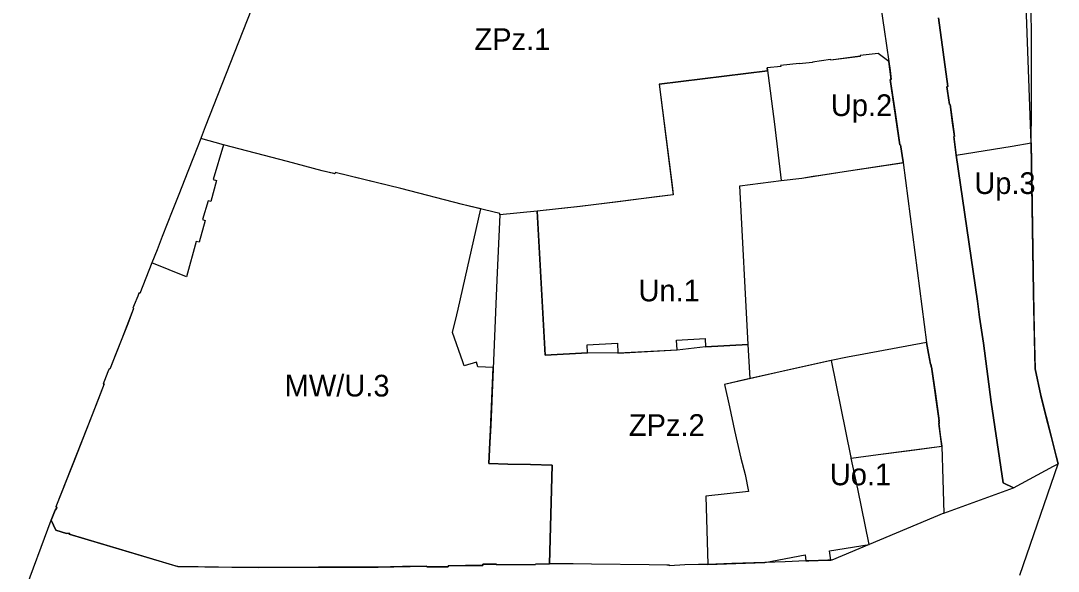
# Model space of a CAD drawing. Extents: x 7423893 to 7425332, y 5547241 to 5548246.
# Drawn here: x 7424408.3 to 7424647.2, y 5547753.2 to 5547880.1 of the extents above; entities that cross this region are included whole.
import ezdxf

# ---------------------------------------------------------------- set-up
doc = ezdxf.new("R2010")
doc.units = 0
for name, color, linetype in [('linie rozgraniczające', 7, 'Continuous'), ('nieprzekraczalne linie zabudowy', 7, 'Continuous'), ('obowiazujace linie zabudowy', 7, 'Continuous'), ('przeznaczenia terenów', 7, 'Continuous')]:
    doc.layers.add(name, color=color, linetype=linetype)

msp = doc.modelspace()

# ---------------------------------------------------------------- linework, layer by layer
at = {"layer": 'linie rozgraniczające'}
for p, q in [((7424638.32, 5547752.33), (7424647.15, 5547777.97)), ((7424620.8, 5547766.62), (7424636.86, 5547772.4)), ((7424408.27, 5547746.17), (7424415.24, 5547764.95))]:
    msp.add_line(p, q, dxfattribs=at)
for points in [[(7424640.9, 5547851.91), (7424640.96, 5547859.51), (7424641.01, 5547867.11), (7424640.96, 5547875.45), (7424640.92, 5547883.78), (7424640.91, 5547890.83), (7424640.89, 5547897.87), (7424640.87, 5547906.66), (7424640.85, 5547915.45), (7424642.77, 5547915.6), (7424646.36, 5547915.88), (7424645.82, 5547923.81), (7424645.28, 5547931.74), (7424644.86, 5547938.7), (7424644.43, 5547945.66), (7424643.77, 5547955.2), (7424643.1, 5547964.73), (7424642.66, 5547971.42), (7424642.22, 5547978.12), (7424641.69, 5547985.83), (7424641.15, 5547993.55), (7424641.11, 5547994.19)], [(7424472.03, 5547910.35), (7424471.85, 5547910.38), (7424469.05, 5547902.62), (7424467.1, 5547897.3), (7424450.71, 5547855.6)], [(7424605.97, 5547885.46), (7424607.07, 5547878.07), (7424608.16, 5547870.67)], [(7424623.68, 5547849.11), (7424623.08, 5547853.39), (7424623.23, 5547853.41), (7424622.74, 5547857.12), (7424622.24, 5547860.82), (7424622.1, 5547860.8), (7424621.82, 5547862.84), (7424621.53, 5547864.88), (7424621.75, 5547864.91), (7424620.66, 5547872.83), (7424619.56, 5547880.75)], [(7424608.16, 5547870.67), (7424605.66, 5547872.52), (7424601.53, 5547872.05), (7424601.55, 5547871.9), (7424594.75, 5547870.99), (7424594.73, 5547871.13), (7424590.59, 5547870.54), (7424590.6, 5547870.47), (7424587.53, 5547870.12), (7424587.51, 5547870.27), (7424583.23, 5547869.76), (7424583.25, 5547869.56), (7424580.16, 5547869.23)], [(7424555.24, 5547865.46), (7424580.24, 5547868.56), (7424580.16, 5547869.23)], [(7424580.16, 5547869.23), (7424581.78, 5547856.23), (7424583.39, 5547843.23), (7424588.08, 5547843.81), (7424590.73, 5547844.24), (7424591.28, 5547844.32), (7424592.38, 5547844.49), (7424597.84, 5547845.33), (7424611.24, 5547847.36), (7424611.44, 5547847.39)], [(7424608.16, 5547870.67), (7424608.43, 5547868.62), (7424608.7, 5547866.58), (7424608.45, 5547866.54), (7424609.57, 5547859), (7424610.68, 5547851.46), (7424610.83, 5547851.49), (7424611.42, 5547847.55), (7424611.44, 5547847.39), (7424611.44, 5547847.39), (7424616.79, 5547805.92), (7424617.26, 5547803.42), (7424617.73, 5547800.91), (7424617.81, 5547800.92), (7424617.87, 5547800.62), (7424617.92, 5547800.33), (7424617.97, 5547800.34), (7424618.86, 5547794.12), (7424619.74, 5547787.9), (7424619.7, 5547787.9), (7424619.65, 5547787.89), (7424619.7, 5547787.58), (7424619.74, 5547787.28), (7424619.68, 5547787.27), (7424619.62, 5547787.26), (7424619.98, 5547784.66), (7424620.34, 5547782.05), (7424620.57, 5547774.33), (7424620.8, 5547766.62)], [(7424555.24, 5547865.46), (7424558.49, 5547839.99), (7424554.63, 5547839.49), (7424545.83, 5547838.38), (7424537.03, 5547837.26), (7424527.14, 5547836.23), (7424518.55, 5547835.36), (7424518.55, 5547835.51), (7424518.55, 5547835.67), (7424515.04, 5547836.5), (7424511.53, 5547837.33), (7424509.96, 5547837.7), (7424495.77, 5547841.39), (7424488.21, 5547843.25), (7424480.64, 5547845.1)], [(7424450.71, 5547855.6), (7424449.8, 5547853.16), (7424449.71, 5547852.92), (7424448.02, 5547848.65), (7424446.72, 5547845.37), (7424444.65, 5547840.02), (7424443.16, 5547836.19), (7424440.85, 5547830.33), (7424439.67, 5547827.29), (7424438.47, 5547824.3), (7424437.08, 5547820.76), (7424435.68, 5547817.23), (7424435.58, 5547817.26), (7424435.48, 5547817.3), (7424435.22, 5547816.59), (7424434.38, 5547814.62), (7424434.07, 5547813.86), (7424434.25, 5547813.79), (7424432.91, 5547810.26), (7424431.57, 5547806.74), (7424430.18, 5547803.28), (7424428.79, 5547799.81), (7424428.61, 5547799.88), (7424428.33, 5547799.16), (7424427.56, 5547797.17), (7424427.26, 5547796.43), (7424427.35, 5547796.4), (7424427.44, 5547796.36), (7424426.08, 5547792.8), (7424424.72, 5547789.25), (7424420.55, 5547778.64), (7424416.38, 5547768.03)], [(7424480.64, 5547845.1), (7424480.56, 5547844.79), (7424480.36, 5547844.84), (7424477.64, 5547845.47), (7424469.71, 5547847.68), (7424454.95, 5547851.45), (7424449.71, 5547852.92)], [(7424623.68, 5547849.11), (7424636.54, 5547851.21), (7424640.9, 5547851.91)], [(7424640.9, 5547851.91), (7424641.04, 5547842.57), (7424641.42, 5547817.37), (7424641.63, 5547808.63), (7424641.84, 5547799.89), (7424643.13, 5547793.71), (7424645.52, 5547784.36), (7424646.7, 5547779.75), (7424647.15, 5547777.97)], [(7424636.86, 5547772.4), (7424634.47, 5547773.59), (7424633.08, 5547782.9), (7424631.7, 5547792.21), (7424629.92, 5547805.78), (7424629.02, 5547811.77), (7424628.56, 5547815.47), (7424623.68, 5547849.11)], [(7424518.55, 5547835.36), (7424517.92, 5547820.4), (7424517.28, 5547805.43), (7424516.48, 5547786.77), (7424516.31, 5547782.87), (7424516.07, 5547778.01), (7424520.42, 5547777.87), (7424525.64, 5547777.79), (7424530.62, 5547777.68), (7424530.33, 5547766.3), (7424530.03, 5547754.92)], [(7424576.19, 5547797.63), (7424575.78, 5547805.43), (7424565.95, 5547804.93), (7424559.37, 5547804.15), (7424545.84, 5547803.5), (7424538.78, 5547803.52), (7424529.04, 5547802.99), (7424527.14, 5547836.23)], [(7424594.87, 5547801.78), (7424584.87, 5547799.55), (7424576.19, 5547797.63), (7424574.86, 5547797.33), (7424570.27, 5547796.26)], [(7424594.87, 5547801.78), (7424597.11, 5547790.79), (7424599.34, 5547779.8), (7424599.46, 5547779.25)], [(7424570.27, 5547796.26), (7424571.46, 5547791.08), (7424572.64, 5547785.65), (7424574.07, 5547779.29), (7424575.03, 5547775.51), (7424575.85, 5547771.6), (7424565.98, 5547770.51), (7424566.5, 5547754.79)], [(7424599.46, 5547779.25), (7424605.68, 5547780.08), (7424613.01, 5547781.07), (7424620.34, 5547782.05)], [(7424636.86, 5547772.4), (7424646.09, 5547777.4), (7424647.15, 5547777.97)], [(7424595.01, 5547755.75), (7424594.8, 5547755.74), (7424594.06, 5547755.73), (7424589.72, 5547755.59), (7424589.02, 5547755.57), (7424584.31, 5547755.4), (7424579.6, 5547755.23), (7424571.96, 5547754.98), (7424566.5, 5547754.79), (7424564.31, 5547754.72), (7424561.2, 5547754.65), (7424557.63, 5547754.46), (7424557.62, 5547754.63), (7424557.49, 5547754.63), (7424557.04, 5547754.64), (7424552.98, 5547754.67), (7424539.7, 5547754.84), (7424535.48, 5547754.88), (7424530.03, 5547754.92), (7424526.82, 5547754.84), (7424526.82, 5547754.72), (7424522.33, 5547754.71), (7424517.84, 5547754.69), (7424517.83, 5547754.81), (7424514.7, 5547754.85), (7424514.68, 5547754.55), (7424510.69, 5547754.49), (7424506.69, 5547754.43), (7424506.69, 5547754.24), (7424504.24, 5547754.21), (7424501.78, 5547754.18), (7424501.78, 5547754.37), (7424496.19, 5547754.27), (7424490.6, 5547754.17), (7424476.85, 5547754.12), (7424463.1, 5547754.06), (7424453.77, 5547754.16), (7424444.43, 5547754.26), (7424444.07, 5547754.37), (7424431.76, 5547758.07), (7424419.45, 5547761.76), (7424419.49, 5547761.97), (7424418.8, 5547761.93), (7424416.35, 5547762.7), (7424415.24, 5547764.95), (7424416.16, 5547767.3), (7424416.47, 5547767.67), (7424416.58, 5547767.95), (7424416.38, 5547768.03)], [(7424620.8, 5547766.62), (7424612.19, 5547762.99), (7424603.58, 5547759.36), (7424595.01, 5547755.75)]]:
    msp.add_lwpolyline(points, dxfattribs=at)
at = {"layer": 'nieprzekraczalne linie zabudowy'}
for p, q in [((7424514.19, 5547836.7), (7424509.96, 5547837.7)), ((7424576.19, 5547797.63), (7424576.19, 5547797.63))]:
    msp.add_line(p, q, dxfattribs=at)
for points in [[(7424640.9, 5547851.91), (7424640.9, 5547851.91), (7424635.99, 5547987.05), (7424635.89, 5547992.77), (7424635.98, 5547992.77), (7424635.97, 5547993.45), (7424635.97, 5547993.45), (7424635.91, 5547998.82), (7424635.47, 5548010.62), (7424635.61, 5548010.62), (7424635.37, 5548017.85)], [(7424555.24, 5547865.46), (7424558.3, 5547841.48), (7424558.49, 5547839.99), (7424537.05, 5547837.26)], [(7424555.24, 5547865.46), (7424558.3, 5547841.48), (7424558.49, 5547839.99)], [(7424647.15, 5547777.97), (7424645.52, 5547784.36), (7424644.4, 5547788.74), (7424643.13, 5547793.71), (7424641.84, 5547799.89), (7424641.42, 5547817.37), (7424640.9, 5547851.91)], [(7424495.77, 5547841.39), (7424480.64, 5547845.1), (7424480.56, 5547844.79), (7424477.64, 5547845.47), (7424469.71, 5547847.68)], [(7424507.71, 5547808.22), (7424508.66, 5547812.27), (7424508.97, 5547813.64), (7424514.19, 5547836.7)], [(7424510.38, 5547800.56), (7424510.07, 5547801.45), (7424507.71, 5547808.22)], [(7424602.39, 5547803.24), (7424598.63, 5547802.51), (7424594.87, 5547801.78), (7424585.53, 5547799.7), (7424570.27, 5547796.26), (7424571.46, 5547791.08), (7424572.64, 5547785.65), (7424574.07, 5547779.29), (7424574.07, 5547779.29), (7424575.03, 5547775.51), (7424575.85, 5547771.6), (7424565.98, 5547770.51), (7424566.5, 5547754.79), (7424572.95, 5547755.01), (7424579.6, 5547755.23)], [(7424530.62, 5547777.68), (7424525.64, 5547777.79), (7424520.42, 5547777.87), (7424516.07, 5547778.01)], [(7424565.98, 5547770.51), (7424566.5, 5547754.79), (7424572.95, 5547755.01)]]:
    msp.add_lwpolyline(points, dxfattribs=at)
at = {"layer": 'obowiazujace linie zabudowy'}
for p, q in [((7424580.24, 5547868.56), (7424555.24, 5547865.46)), ((7424580.24, 5547868.56), (7424555.24, 5547865.46)), ((7424469.71, 5547847.68), (7424454.95, 5547851.45)), ((7424509.96, 5547837.7), (7424495.77, 5547841.39)), ((7424530.03, 5547754.92), (7424530.62, 5547777.68))]:
    msp.add_line(p, q, dxfattribs=at)
for points in [[(7424619.56, 5547880.75), (7424621.75, 5547864.91), (7424621.53, 5547864.88), (7424622.1, 5547860.8), (7424622.24, 5547860.82), (7424623.23, 5547853.41), (7424623.08, 5547853.39), (7424623.68, 5547849.11), (7424628.56, 5547815.47), (7424629.02, 5547811.77), (7424629.92, 5547805.78), (7424631.7, 5547792.21), (7424634.47, 5547773.59), (7424636.86, 5547772.4), (7424646.09, 5547777.4), (7424647.15, 5547777.97)], [(7424605.66, 5547872.52), (7424601.53, 5547872.05), (7424601.55, 5547871.88), (7424594.75, 5547870.99), (7424594.73, 5547871.16), (7424590.59, 5547870.54), (7424590.6, 5547870.47), (7424587.53, 5547870.12), (7424587.51, 5547870.27), (7424583.23, 5547869.76), (7424583.25, 5547869.56), (7424580.16, 5547869.23), (7424580.24, 5547868.56)], [(7424611.44, 5547847.39), (7424611.42, 5547847.55), (7424610.83, 5547851.49), (7424610.68, 5547851.46), (7424608.45, 5547866.54), (7424608.7, 5547866.58), (7424608.16, 5547870.67), (7424605.66, 5547872.52)], [(7424611.44, 5547847.39), (7424611.42, 5547847.55), (7424610.83, 5547851.49), (7424610.68, 5547851.46), (7424608.45, 5547866.54), (7424608.7, 5547866.58), (7424608.16, 5547870.67), (7424605.66, 5547872.52)], [(7424454.95, 5547851.45), (7424452.6, 5547843.52), (7424453.36, 5547843.3), (7424452.03, 5547838.44), (7424451.44, 5547838.6), (7424450.09, 5547834.26), (7424450.7, 5547834.07), (7424449.33, 5547829.04), (7424448.65, 5547829.22), (7424446.42, 5547821.05), (7424438.47, 5547824.3), (7424435.68, 5547817.23), (7424435.48, 5547817.3), (7424435.22, 5547816.59), (7424434.38, 5547814.62), (7424434.07, 5547813.86), (7424434.25, 5547813.79), (7424431.57, 5547806.74), (7424428.79, 5547799.81), (7424428.61, 5547799.88), (7424428.33, 5547799.16), (7424427.56, 5547797.17), (7424427.26, 5547796.43), (7424427.44, 5547796.36), (7424424.72, 5547789.25), (7424416.38, 5547768.03), (7424416.58, 5547767.95), (7424416.47, 5547767.67), (7424416.16, 5547767.3), (7424415.24, 5547764.95)], [(7424529.04, 5547802.99), (7424538.78, 5547803.52), (7424538.68, 5547805.41), (7424545.65, 5547805.79), (7424545.76, 5547803.5), (7424559.37, 5547804.2), (7424559.26, 5547806.49), (7424565.85, 5547806.83), (7424565.95, 5547804.93), (7424575.78, 5547805.43), (7424575.78, 5547805.43), (7424573.87, 5547842.01), (7424583.39, 5547843.23), (7424588.08, 5547843.81), (7424597.84, 5547845.32), (7424611.44, 5547847.39)], [(7424537.05, 5547837.26), (7424537.05, 5547837.26), (7424537.05, 5547837.26), (7424527.14, 5547836.23), (7424529.04, 5547802.99)], [(7424579.6, 5547755.23), (7424588.86, 5547756.97), (7424589.02, 5547755.57), (7424589.72, 5547755.59), (7424594.06, 5547755.73), (7424594.8, 5547755.74), (7424594.48, 5547757.9), (7424603.58, 5547759.36), (7424600.97, 5547772.19), (7424599.46, 5547779.25), (7424605.68, 5547780.08), (7424620.34, 5547782.05), (7424619.62, 5547787.26), (7424619.74, 5547787.28), (7424619.65, 5547787.89), (7424619.74, 5547787.9), (7424617.97, 5547800.34), (7424617.92, 5547800.33), (7424617.81, 5547800.92), (7424617.73, 5547800.91), (7424617.26, 5547803.42), (7424616.79, 5547805.92), (7424602.39, 5547803.24)], [(7424516.07, 5547778.01), (7424516.31, 5547782.87), (7424516.44, 5547785.8), (7424517.06, 5547800.19), (7424513.5, 5547800.3), (7424513.18, 5547801.38), (7424510.38, 5547800.56)], [(7424415.24, 5547764.95), (7424416.35, 5547762.7), (7424418.8, 5547761.93), (7424419.49, 5547761.97), (7424419.45, 5547761.76), (7424444.43, 5547754.26), (7424463.1, 5547754.06), (7424476.85, 5547754.12), (7424490.6, 5547754.17), (7424494.14, 5547754.23), (7424501.78, 5547754.37), (7424501.78, 5547754.18), (7424506.69, 5547754.24), (7424506.69, 5547754.43), (7424514.68, 5547754.55), (7424514.7, 5547754.85), (7424517.83, 5547754.81), (7424517.84, 5547754.69), (7424526.82, 5547754.72), (7424526.82, 5547754.84), (7424530.03, 5547754.92)]]:
    msp.add_lwpolyline(points, dxfattribs=at)

# ---------------------------------------------------------------- texts
at = {"layer": 'przeznaczenia terenów'}
for s, p in [('ZPz.1', (7424512.74, 5547873.34)), ('Up.2', (7424594.8, 5547858.12)), ('Up.3', (7424627.82, 5547840.15)), ('Un.1', (7424550.5, 5547815.41)), ('MW/U.3', (7424469.04, 5547793.48)), ('ZPz.2', (7424548.28, 5547784.4)), ('Uo.1', (7424594.55, 5547773.02))]:
    msp.add_text(s, height=5, dxfattribs=at).set_placement(p)

doc.saveas('drawing.dxf')
